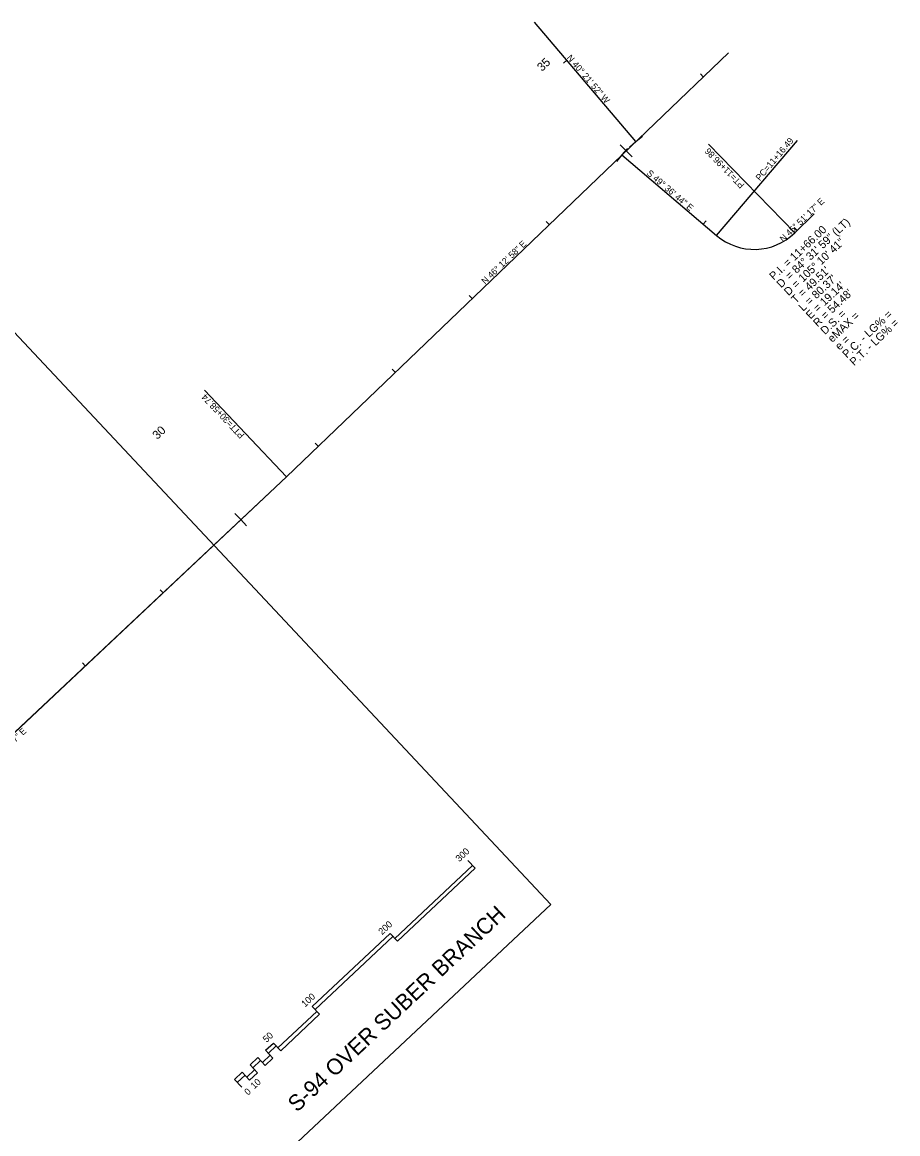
# Model space of a CAD drawing. Extents: x 1623239 to 1625698, y 1118659 to 1120751.
# Drawn here: x 1624877 to 1625698, y 1119709 to 1120751 of the extents above; entities that cross this region are included whole.
import ezdxf

# ---------------------------------------------------------------- set-up
doc = ezdxf.new("R2010")
doc.units = 0
for name, color, linetype in [('Default', 7, 'Continuous'), ('RD_HC_Cl', 7, 'Continuous'), ('RD_HC_Data', 7, 'Continuous'), ('RD_HC_Data_Tic', 7, 'Continuous'), ('RD_HC_TX_Sta50', 7, 'Continuous'), ('RD_SHT_ShtClip', 7, 'Continuous'), ('RD_SHT_TX', 7, 'Continuous')]:
    doc.layers.add(name, color=color, linetype=linetype)

# ---------------------------------------------------------------- blocks, each defined once
blk = doc.blocks.new('GSC050')
at = {"layer": 'Default'}
for p, q in [((0, -96), (0, 0)), ((0, 0), (96, 0)), ((96, -96), (96, 0)), ((192, -96), (192, 0)), ((192, 0), (288, 0)), ((288, -96), (288, 0)), ((384, -96), (384, 0)), ((384, 0), (480, 0)), ((480, 0), (480, -96)), ((960, -96), (960, 0)), ((960, 0), (1920, 0)), ((1920, -96), (1920, 0)), ((2880, 0), (2880, -96)), ((0, -36), (96, -36)), ((96, -60), (192, -60)), ((96, -96), (192, -96)), ((192, -36), (288, -36)), ((288, -60), (384, -60)), ((288, -96), (384, -96)), ((384, -36), (480, -36)), ((480, -60), (960, -60)), ((480, -96), (960, -96)), ((960, -36), (1920, -36)), ((1920, -60), (2880, -60)), ((1920, -96), (2880, -96))]:
    blk.add_line(p, q, dxfattribs=at)
for s, p in [('50', (434.7951, 42)), ('300', (2812.4727, 42)), ('100', (906.0396, 38)), ('200', (1856.4727, 38)), ('0', (-10.882, -190)), ('10', (68.362, -187.6))]:
    blk.add_text(s, height=60, dxfattribs=at).set_placement(p)

msp = doc.modelspace()

# ---------------------------------------------------------------- linework, layer by layer
at = {"layer": 'RD_HC_Cl'}
for p, q in [((1625452.3, 1120638.9), (1625357.3, 1120750.8)), ((1625124.7, 1120324.9), (1625539.1, 1120722.2)), ((1625124.7, 1120324.9), (1625539.1, 1120722.2)), ((1625439.2, 1120626.4), (1625527.9, 1120550.9)), ((1625601.2, 1120553.3), (1625619.5, 1120571.1)), ((1624678.7, 1119905.1), (1625124.7, 1120324.9)), ((1624870.5, 1120085.7), (1625124.7, 1120324.9))]:
    msp.add_line(p, q, dxfattribs=at)
msp.add_arc((1625563.2, 1120592.4), 54.5, 229.6121, 314.1453, dxfattribs=at)
at = {"layer": 'RD_HC_Data'}
for p, q in [((1625527.9, 1120550.9), (1625603.6, 1120639.8)), ((1625601.2, 1120553.3), (1625520.4, 1120636.5)), ((1625124.7, 1120324.9), (1625048, 1120406))]:
    msp.add_line(p, q, dxfattribs=at)
at = {"layer": 'RD_HC_Data_Tic'}
for p, q in [((1625387.5, 1120715.1), (1625384.5, 1120712.5)), ((1625515.4, 1120699.5), (1625512.7, 1120702.3)), ((1625452.3, 1120638.9), (1625458.4, 1120644.1)), ((1625443.2, 1120630.3), (1625437.7, 1120636)), ((1625439.2, 1120626.4), (1625444.4, 1120632.5)), ((1625443.2, 1120630.3), (1625448.8, 1120624.5)), ((1625452.3, 1120638.9), (1625446.2, 1120633.8)), ((1625439.2, 1120626.4), (1625434, 1120620.3)), ((1625371, 1120561.1), (1625368.3, 1120564)), ((1625515.4, 1120561.6), (1625518, 1120564.7)), ((1625603.4, 1120555.5), (1625600.6, 1120558.4)), ((1625298.8, 1120491.9), (1625296.1, 1120494.8)), ((1625226.7, 1120422.7), (1625223.9, 1120425.6)), ((1625154.5, 1120353.5), (1625151.7, 1120356.4)), ((1625081.9, 1120284.7), (1625076.4, 1120290.5)), ((1625081.9, 1120284.7), (1625087.4, 1120278.8)), ((1625009.1, 1120216.1), (1625006.3, 1120219)), ((1624936.3, 1120147.6), (1624933.5, 1120150.5))]:
    msp.add_line(p, q, dxfattribs=at)
at = {"layer": 'RD_SHT_ShtClip'}
msp.add_lwpolyline([(1623307.1, 1119494.9), (1624620.1, 1120726.2), (1625372.5, 1119923.9), (1624059.6, 1118692.6)], close=True, dxfattribs=at)

# ---------------------------------------------------------------- block references
at = {"layer": 'RD_SHT_TX', "xscale": 0.10416176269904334, "yscale": 0.10416176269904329, "rotation": 43.162669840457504}
msp.add_blockref('GSC050', (1625076.1, 1119760), dxfattribs=at)

# ---------------------------------------------------------------- texts
at = {"layer": 'RD_HC_Data'}
for s, height, rotation, p in [('N 40%%d 21\' 52" W', 6, 310.3644, (1625387.1, 1120717.2)), ('PC=11+16.49', 6, 49.6121, (1625568.5, 1120601.7)), ('PT=11+96.86', 6, 134.1453, (1625554.5, 1120598.6)), ('S 49%%d 36\' 44" E', 6, 319.6121, (1625461.9, 1120608.4)), ('N 45%%d 51\' 17" E', 6, 44.1453, (1625590.5, 1120544.4)), ('P.I. = 11+66.00', 7.5, 43.1627, (1625581.6, 1120508.6)), ('    = 84%%d 31\' 59" (LT)', 7.5, 43.1627, (1625588.4, 1120501.3)), ('N 46%%d 12\' 58" E', 6, 43.7838, (1625310.9, 1120504.8)), ('D = 105%%d 10\' 41"', 7.5, 43.1627, (1625595.3, 1120494)), ("T = 49.51'", 7.5, 43.1627, (1625602.1, 1120486.7)), ("L = 80.37'", 7.5, 43.1627, (1625609, 1120479.4)), ('D', 7.5, 43.1627, (1625588.4, 1120501.3)), ("E = 19.14'", 7.5, 43.1627, (1625615.8, 1120472.1)), ("R = 54.48'", 7.5, 43.1627, (1625622.6, 1120464.8)), ('D.S. = ', 7.5, 43.1627, (1625629.5, 1120457.5)), ('eMAX = ', 7.5, 43.1627, (1625636.3, 1120450.2)), ('P.C. - LG% = ', 7.5, 43.1627, (1625650, 1120435.6)), ('P.T. - LG% = ', 7.5, 43.1627, (1625656.9, 1120428.3)), ('e = ', 7.5, 43.1627, (1625643.2, 1120442.9)), ('PTT=30+58.74', 6, 133.4099, (1625085.8, 1120364.1)), ('N 46%%d 43\' 57" E', 6, 43.2675, (1624842, 1120048.5))]:
    msp.add_text(s, height=height, rotation=rotation, dxfattribs=at).set_placement(p)
at = {"layer": 'RD_HC_TX_Sta50'}
for s, rotation, p in [('35', 43.7838, (1625364.3, 1120704.2)), ('30', 43.2675, (1625003.7, 1120359.3))]:
    msp.add_text(s, height=8, rotation=rotation, dxfattribs=at).set_placement(p)
at = {"layer": 'RD_SHT_TX'}
msp.add_text('S-94 OVER SUBER BRANCH', height=15, rotation=43.1627, dxfattribs=at).set_placement((1625134.7, 1119728.7))

doc.saveas('drawing.dxf')
